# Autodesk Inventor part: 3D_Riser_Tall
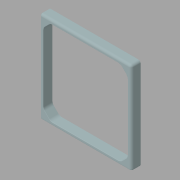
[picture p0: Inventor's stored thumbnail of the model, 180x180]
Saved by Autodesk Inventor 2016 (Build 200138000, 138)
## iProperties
Created: 2016-01
Part Number: 3D_Riser_Tall
Material: Generic
Document SubType Name: Modeling
Designer: John
Density: 1 g/cm^3
Appearance: Default
Author: John
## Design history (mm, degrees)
feature "SOLID1"
body "Solid1"
